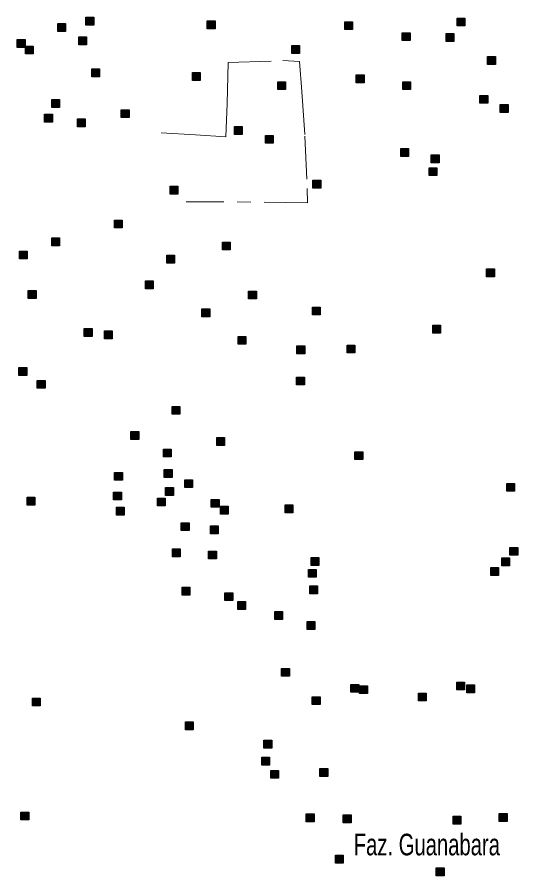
# Model space of a CAD drawing. Extents: x 445.6 to 500, y 8618.1 to 8673.4.
# Drawn here: x 461.6 to 465.3, y 8644.29 to 8650.65 of the extents above; entities that cross this region are included whole.
import ezdxf

# ---------------------------------------------------------------- set-up
doc = ezdxf.new("R2010")
doc.units = 0
doc.header["$LTSCALE"] = 0.064
doc.linetypes.add('DOT_DASHED', pattern=[7.7, 5, -1.2, 0.3, -1.2])
doc.layers.add('2', color=7, linetype='Continuous', lineweight=25)
doc.layers.add('22', color=7, linetype='DOT_DASHED', lineweight=13)
doc.layers.add('61', color=7, linetype='Continuous')

msp = doc.modelspace()

# ---------------------------------------------------------------- hatches: boundary and pattern name
at = {"layer": '2'}
for points in [[(462.1077, 8650.6478), (462.1657, 8650.6478), (462.1657, 8650.5898), (462.1077, 8650.5898)], [(464.8549, 8650.6411), (464.9129, 8650.6411), (464.9129, 8650.5831), (464.8549, 8650.5831)], [(461.9001, 8650.6003), (461.9581, 8650.6003), (461.9581, 8650.5423), (461.9001, 8650.5423)], [(463.0062, 8650.6207), (463.0642, 8650.6207), (463.0642, 8650.5627), (463.0062, 8650.5627)], [(464.0239, 8650.614), (464.0819, 8650.614), (464.0819, 8650.556), (464.0239, 8650.556)], [(462.0554, 8650.502), (462.1134, 8650.502), (462.1134, 8650.444), (462.0554, 8650.444)], [(464.4496, 8650.5327), (464.5076, 8650.5327), (464.5076, 8650.4747), (464.4496, 8650.4747)], [(464.7738, 8650.5259), (464.8318, 8650.5259), (464.8318, 8650.4679), (464.7738, 8650.4679)], [(461.5994, 8650.4817), (461.6574, 8650.4817), (461.6574, 8650.4237), (461.5994, 8650.4237)], [(463.6311, 8650.4377), (463.6891, 8650.4377), (463.6891, 8650.3797), (463.6311, 8650.3797)], [(461.6602, 8650.4343), (461.7182, 8650.4343), (461.7182, 8650.3763), (461.6602, 8650.3763)], [(465.0812, 8650.3565), (465.1392, 8650.3565), (465.1392, 8650.2985), (465.0812, 8650.2985)], [(462.1516, 8650.2649), (462.2096, 8650.2649), (462.2096, 8650.2069), (462.1516, 8650.2069)], [(462.897, 8650.2375), (462.955, 8650.2375), (462.955, 8650.1795), (462.897, 8650.1795)], [(464.1087, 8650.2205), (464.1667, 8650.2205), (464.1667, 8650.1625), (464.1087, 8650.1625)], [(463.5286, 8650.1697), (463.5866, 8650.1697), (463.5866, 8650.1117), (463.5286, 8650.1117)], [(464.4533, 8650.1697), (464.5113, 8650.1697), (464.5113, 8650.1117), (464.4533, 8650.1117)], [(465.0238, 8650.0685), (465.0818, 8650.0685), (465.0818, 8650.0105), (465.0238, 8650.0105)], [(461.8557, 8650.0378), (461.9137, 8650.0378), (461.9137, 8649.9798), (461.8557, 8649.9798)], [(465.1746, 8650.0007), (465.2326, 8650.0007), (465.2326, 8649.9427), (465.1746, 8649.9427)], [(461.8017, 8649.9294), (461.8597, 8649.9294), (461.8597, 8649.8714), (461.8017, 8649.8714)], [(462.3691, 8649.9633), (462.4271, 8649.9633), (462.4271, 8649.9053), (462.3691, 8649.9053)], [(462.0449, 8649.8955), (462.1029, 8649.8955), (462.1029, 8649.8375), (462.0449, 8649.8375)], [(463.2069, 8649.8377), (463.2649, 8649.8377), (463.2649, 8649.7797), (463.2069, 8649.7797)], [(463.4365, 8649.7733), (463.4945, 8649.7733), (463.4945, 8649.7153), (463.4365, 8649.7153)], [(464.4383, 8649.6754), (464.4963, 8649.6754), (464.4963, 8649.6174), (464.4383, 8649.6174)], [(464.6646, 8649.628), (464.7226, 8649.628), (464.7226, 8649.57), (464.6646, 8649.57)], [(464.6477, 8649.5331), (464.7057, 8649.5331), (464.7057, 8649.4751), (464.6477, 8649.4751)], [(463.7878, 8649.4413), (463.8458, 8649.4413), (463.8458, 8649.3833), (463.7878, 8649.3833)], [(462.7306, 8649.3973), (462.7886, 8649.3973), (462.7886, 8649.3393), (462.7306, 8649.3393)], [(462.3194, 8649.1466), (462.3774, 8649.1466), (462.3774, 8649.0886), (462.3194, 8649.0886)], [(461.8557, 8649.0146), (461.9137, 8649.0146), (461.9137, 8648.9566), (461.8557, 8648.9566)], [(463.119, 8648.9839), (463.177, 8648.9839), (463.177, 8648.9259), (463.119, 8648.9259)], [(461.6159, 8648.9164), (461.6739, 8648.9164), (461.6739, 8648.8584), (461.6159, 8648.8584)], [(462.7069, 8648.8857), (462.7649, 8648.8857), (462.7649, 8648.8277), (462.7069, 8648.8277)], [(465.0733, 8648.7844), (465.1313, 8648.7844), (465.1313, 8648.7264), (465.0733, 8648.7264)], [(462.5491, 8648.696), (462.6071, 8648.696), (462.6071, 8648.638), (462.5491, 8648.638)], [(461.681, 8648.6245), (461.739, 8648.6245), (461.739, 8648.5665), (461.681, 8648.5665)], [(463.3116, 8648.6214), (463.3696, 8648.6214), (463.3696, 8648.5634), (463.3116, 8648.5634)], [(462.967, 8648.4893), (463.025, 8648.4893), (463.025, 8648.4313), (462.967, 8648.4313)], [(463.7845, 8648.5028), (463.8425, 8648.5028), (463.8425, 8648.4448), (463.7845, 8648.4448)], [(462.0964, 8648.3436), (462.1544, 8648.3436), (462.1544, 8648.2856), (462.0964, 8648.2856)], [(464.6753, 8648.3681), (464.7333, 8648.3681), (464.7333, 8648.3101), (464.6753, 8648.3101)], [(462.2451, 8648.3267), (462.3031, 8648.3267), (462.3031, 8648.2687), (462.2451, 8648.2687)], [(463.2348, 8648.286), (463.2928, 8648.286), (463.2928, 8648.228), (463.2348, 8648.228)], [(463.6696, 8648.2148), (463.7276, 8648.2148), (463.7276, 8648.1568), (463.6696, 8648.1568)], [(464.0412, 8648.2216), (464.0992, 8648.2216), (464.0992, 8648.1636), (464.0412, 8648.1636)], [(461.6122, 8648.0553), (461.6702, 8648.0553), (461.6702, 8647.9973), (461.6122, 8647.9973)], [(461.7478, 8647.9598), (461.8058, 8647.9598), (461.8058, 8647.9018), (461.7478, 8647.9018)], [(463.6671, 8647.9843), (463.7251, 8647.9843), (463.7251, 8647.9263), (463.6671, 8647.9263)], [(462.7457, 8647.7673), (462.8037, 8647.7673), (462.8037, 8647.7093), (462.7457, 8647.7093)], [(462.4417, 8647.5809), (462.4997, 8647.5809), (462.4997, 8647.5229), (462.4417, 8647.5229)], [(463.0767, 8647.5369), (463.1347, 8647.5369), (463.1347, 8647.4789), (463.0767, 8647.4789)], [(462.6815, 8647.4522), (462.7395, 8647.4522), (462.7395, 8647.3942), (462.6815, 8647.3942)], [(464.0994, 8647.4321), (464.1574, 8647.4321), (464.1574, 8647.3741), (464.0994, 8647.3741)], [(462.3201, 8647.2794), (462.3781, 8647.2794), (462.3781, 8647.2214), (462.3201, 8647.2214)], [(462.6882, 8647.2997), (462.7462, 8647.2997), (462.7462, 8647.2417), (462.6882, 8647.2417)], [(462.8402, 8647.2252), (462.8982, 8647.2252), (462.8982, 8647.1672), (462.8402, 8647.1672)], [(465.2232, 8647.1983), (465.2812, 8647.1983), (465.2812, 8647.1403), (465.2232, 8647.1403)], [(462.3133, 8647.1337), (462.3713, 8647.1337), (462.3713, 8647.0757), (462.3133, 8647.0757)], [(462.6984, 8647.1676), (462.7564, 8647.1676), (462.7564, 8647.1096), (462.6984, 8647.1096)], [(461.6731, 8647.0955), (461.7311, 8647.0955), (461.7311, 8647.0375), (461.6731, 8647.0375)], [(462.6376, 8647.0897), (462.6956, 8647.0897), (462.6956, 8647.0317), (462.6376, 8647.0317)], [(463.0362, 8647.0795), (463.0942, 8647.0795), (463.0942, 8647.0215), (463.0362, 8647.0215)], [(462.3336, 8647.0219), (462.3916, 8647.0219), (462.3916, 8646.9639), (462.3336, 8646.9639)], [(463.1037, 8647.0287), (463.1617, 8647.0287), (463.1617, 8646.9707), (463.1037, 8646.9707)], [(463.5826, 8647.0391), (463.6406, 8647.0391), (463.6406, 8646.9811), (463.5826, 8646.9811)], [(462.8132, 8646.9067), (462.8712, 8646.9067), (462.8712, 8646.8487), (462.8132, 8646.8487)], [(463.0294, 8646.883), (463.0874, 8646.883), (463.0874, 8646.825), (463.0294, 8646.825)], [(462.749, 8646.7136), (462.807, 8646.7136), (462.807, 8646.6556), (462.749, 8646.6556)], [(463.0159, 8646.6967), (463.0739, 8646.6967), (463.0739, 8646.6387), (463.0159, 8646.6387)], [(465.2469, 8646.724), (465.3049, 8646.724), (465.3049, 8646.666), (465.2469, 8646.666)], [(463.7752, 8646.6495), (463.8332, 8646.6495), (463.8332, 8646.5915), (463.7752, 8646.5915)], [(465.1861, 8646.6461), (465.2441, 8646.6461), (465.2441, 8646.5881), (465.1861, 8646.5881)], [(463.7549, 8646.5614), (463.8129, 8646.5614), (463.8129, 8646.5034), (463.7549, 8646.5034)], [(465.105, 8646.5749), (465.163, 8646.5749), (465.163, 8646.5169), (465.105, 8646.5169)], [(463.765, 8646.4394), (463.823, 8646.4394), (463.823, 8646.3814), (463.765, 8646.3814)], [(462.82, 8646.429), (462.878, 8646.429), (462.878, 8646.371), (462.82, 8646.371)], [(463.1375, 8646.3883), (463.1955, 8646.3883), (463.1955, 8646.3303), (463.1375, 8646.3303)], [(463.2321, 8646.324), (463.2901, 8646.324), (463.2901, 8646.266), (463.2321, 8646.266)], [(463.5057, 8646.2494), (463.5637, 8646.2494), (463.5637, 8646.1914), (463.5057, 8646.1914)], [(463.7448, 8646.1751), (463.8028, 8646.1751), (463.8028, 8646.1171), (463.7448, 8646.1171)], [(463.5565, 8645.8292), (463.6145, 8645.8292), (463.6145, 8645.7712), (463.5565, 8645.7712)], [(464.07, 8645.7107), (464.128, 8645.7107), (464.128, 8645.6527), (464.07, 8645.6527)], [(464.1341, 8645.7005), (464.1921, 8645.7005), (464.1921, 8645.6425), (464.1341, 8645.6425)], [(464.853, 8645.7276), (464.911, 8645.7276), (464.911, 8645.6696), (464.853, 8645.6696)], [(464.9273, 8645.7073), (464.9853, 8645.7073), (464.9853, 8645.6493), (464.9273, 8645.6493)], [(461.7119, 8645.6088), (461.7699, 8645.6088), (461.7699, 8645.5508), (461.7119, 8645.5508)], [(463.7828, 8645.6192), (463.8408, 8645.6192), (463.8408, 8645.5612), (463.7828, 8645.5612)], [(464.5693, 8645.6463), (464.6273, 8645.6463), (464.6273, 8645.5883), (464.5693, 8645.5883)], [(462.8449, 8645.4328), (462.9029, 8645.4328), (462.9029, 8645.3748), (462.8449, 8645.3748)], [(463.4259, 8645.2973), (463.4839, 8645.2973), (463.4839, 8645.2393), (463.4259, 8645.2393)], [(463.409, 8645.1719), (463.467, 8645.1719), (463.467, 8645.1139), (463.409, 8645.1139)], [(463.4765, 8645.0737), (463.5345, 8645.0737), (463.5345, 8645.0157), (463.4765, 8645.0157)], [(463.8403, 8645.0873), (463.8983, 8645.0873), (463.8983, 8645.0293), (463.8403, 8645.0293)], [(461.6275, 8644.7652), (461.6855, 8644.7652), (461.6855, 8644.7072), (461.6275, 8644.7072)], [(463.7389, 8644.7518), (463.7969, 8644.7518), (463.7969, 8644.6938), (463.7389, 8644.6938)], [(464.0125, 8644.7451), (464.0705, 8644.7451), (464.0705, 8644.6871), (464.0125, 8644.6871)], [(464.826, 8644.7349), (464.884, 8644.7349), (464.884, 8644.6769), (464.826, 8644.6769)], [(465.1671, 8644.7552), (465.2251, 8644.7552), (465.2251, 8644.6972), (465.1671, 8644.6972)], [(463.9551, 8644.4469), (464.0131, 8644.4469), (464.0131, 8644.3889), (463.9551, 8644.3889)], [(464.701, 8644.3521), (464.759, 8644.3521), (464.759, 8644.2941), (464.701, 8644.2941)]]:
    msp.add_hatch(color=256, dxfattribs=at).paths.add_polyline_path(points)

# ---------------------------------------------------------------- linework, layer by layer
for points in [[(462.1077, 8650.6478), (462.1657, 8650.6478), (462.1657, 8650.5898), (462.1077, 8650.5898)], [(464.8549, 8650.6411), (464.9129, 8650.6411), (464.9129, 8650.5831), (464.8549, 8650.5831)], [(461.9001, 8650.6003), (461.9581, 8650.6003), (461.9581, 8650.5423), (461.9001, 8650.5423)], [(463.0062, 8650.6207), (463.0642, 8650.6207), (463.0642, 8650.5627), (463.0062, 8650.5627)], [(464.0239, 8650.614), (464.0819, 8650.614), (464.0819, 8650.556), (464.0239, 8650.556)], [(462.0554, 8650.502), (462.1134, 8650.502), (462.1134, 8650.444), (462.0554, 8650.444)], [(464.4496, 8650.5327), (464.5076, 8650.5327), (464.5076, 8650.4747), (464.4496, 8650.4747)], [(464.7738, 8650.5259), (464.8318, 8650.5259), (464.8318, 8650.4679), (464.7738, 8650.4679)], [(461.5994, 8650.4817), (461.6574, 8650.4817), (461.6574, 8650.4237), (461.5994, 8650.4237)], [(463.6311, 8650.4377), (463.6891, 8650.4377), (463.6891, 8650.3797), (463.6311, 8650.3797)], [(461.6602, 8650.4343), (461.7182, 8650.4343), (461.7182, 8650.3763), (461.6602, 8650.3763)], [(465.0812, 8650.3565), (465.1392, 8650.3565), (465.1392, 8650.2985), (465.0812, 8650.2985)], [(462.1516, 8650.2649), (462.2096, 8650.2649), (462.2096, 8650.2069), (462.1516, 8650.2069)], [(462.897, 8650.2375), (462.955, 8650.2375), (462.955, 8650.1795), (462.897, 8650.1795)], [(464.1087, 8650.2205), (464.1667, 8650.2205), (464.1667, 8650.1625), (464.1087, 8650.1625)], [(463.5286, 8650.1697), (463.5866, 8650.1697), (463.5866, 8650.1117), (463.5286, 8650.1117)], [(464.4533, 8650.1697), (464.5113, 8650.1697), (464.5113, 8650.1117), (464.4533, 8650.1117)], [(465.0238, 8650.0685), (465.0818, 8650.0685), (465.0818, 8650.0105), (465.0238, 8650.0105)], [(461.8557, 8650.0378), (461.9137, 8650.0378), (461.9137, 8649.9798), (461.8557, 8649.9798)], [(465.1746, 8650.0007), (465.2326, 8650.0007), (465.2326, 8649.9427), (465.1746, 8649.9427)], [(461.8017, 8649.9294), (461.8597, 8649.9294), (461.8597, 8649.8714), (461.8017, 8649.8714)], [(462.3691, 8649.9633), (462.4271, 8649.9633), (462.4271, 8649.9053), (462.3691, 8649.9053)], [(462.0449, 8649.8955), (462.1029, 8649.8955), (462.1029, 8649.8375), (462.0449, 8649.8375)], [(463.2069, 8649.8377), (463.2649, 8649.8377), (463.2649, 8649.7797), (463.2069, 8649.7797)], [(463.4365, 8649.7733), (463.4945, 8649.7733), (463.4945, 8649.7153), (463.4365, 8649.7153)], [(464.4383, 8649.6754), (464.4963, 8649.6754), (464.4963, 8649.6174), (464.4383, 8649.6174)], [(464.6646, 8649.628), (464.7226, 8649.628), (464.7226, 8649.57), (464.6646, 8649.57)], [(464.6477, 8649.5331), (464.7057, 8649.5331), (464.7057, 8649.4751), (464.6477, 8649.4751)], [(463.7878, 8649.4413), (463.8458, 8649.4413), (463.8458, 8649.3833), (463.7878, 8649.3833)], [(462.7306, 8649.3973), (462.7886, 8649.3973), (462.7886, 8649.3393), (462.7306, 8649.3393)], [(462.3194, 8649.1466), (462.3774, 8649.1466), (462.3774, 8649.0886), (462.3194, 8649.0886)], [(461.8557, 8649.0146), (461.9137, 8649.0146), (461.9137, 8648.9566), (461.8557, 8648.9566)], [(463.119, 8648.9839), (463.177, 8648.9839), (463.177, 8648.9259), (463.119, 8648.9259)], [(461.6159, 8648.9164), (461.6739, 8648.9164), (461.6739, 8648.8584), (461.6159, 8648.8584)], [(462.7069, 8648.8857), (462.7649, 8648.8857), (462.7649, 8648.8277), (462.7069, 8648.8277)], [(465.0733, 8648.7844), (465.1313, 8648.7844), (465.1313, 8648.7264), (465.0733, 8648.7264)], [(462.5491, 8648.696), (462.6071, 8648.696), (462.6071, 8648.638), (462.5491, 8648.638)], [(461.681, 8648.6245), (461.739, 8648.6245), (461.739, 8648.5665), (461.681, 8648.5665)], [(463.3116, 8648.6214), (463.3696, 8648.6214), (463.3696, 8648.5634), (463.3116, 8648.5634)], [(462.967, 8648.4893), (463.025, 8648.4893), (463.025, 8648.4313), (462.967, 8648.4313)], [(463.7845, 8648.5028), (463.8425, 8648.5028), (463.8425, 8648.4448), (463.7845, 8648.4448)], [(462.0964, 8648.3436), (462.1544, 8648.3436), (462.1544, 8648.2856), (462.0964, 8648.2856)], [(464.6753, 8648.3681), (464.7333, 8648.3681), (464.7333, 8648.3101), (464.6753, 8648.3101)], [(462.2451, 8648.3267), (462.3031, 8648.3267), (462.3031, 8648.2687), (462.2451, 8648.2687)], [(463.2348, 8648.286), (463.2928, 8648.286), (463.2928, 8648.228), (463.2348, 8648.228)], [(463.6696, 8648.2148), (463.7276, 8648.2148), (463.7276, 8648.1568), (463.6696, 8648.1568)], [(464.0412, 8648.2216), (464.0992, 8648.2216), (464.0992, 8648.1636), (464.0412, 8648.1636)], [(461.6122, 8648.0553), (461.6702, 8648.0553), (461.6702, 8647.9973), (461.6122, 8647.9973)], [(461.7478, 8647.9598), (461.8058, 8647.9598), (461.8058, 8647.9018), (461.7478, 8647.9018)], [(463.6671, 8647.9843), (463.7251, 8647.9843), (463.7251, 8647.9263), (463.6671, 8647.9263)], [(462.7457, 8647.7673), (462.8037, 8647.7673), (462.8037, 8647.7093), (462.7457, 8647.7093)], [(462.4417, 8647.5809), (462.4997, 8647.5809), (462.4997, 8647.5229), (462.4417, 8647.5229)], [(463.0767, 8647.5369), (463.1347, 8647.5369), (463.1347, 8647.4789), (463.0767, 8647.4789)], [(462.6815, 8647.4522), (462.7395, 8647.4522), (462.7395, 8647.3942), (462.6815, 8647.3942)], [(464.0994, 8647.4321), (464.1574, 8647.4321), (464.1574, 8647.3741), (464.0994, 8647.3741)], [(462.3201, 8647.2794), (462.3781, 8647.2794), (462.3781, 8647.2214), (462.3201, 8647.2214)], [(462.6882, 8647.2997), (462.7462, 8647.2997), (462.7462, 8647.2417), (462.6882, 8647.2417)], [(462.8402, 8647.2252), (462.8982, 8647.2252), (462.8982, 8647.1672), (462.8402, 8647.1672)], [(465.2232, 8647.1983), (465.2812, 8647.1983), (465.2812, 8647.1403), (465.2232, 8647.1403)], [(462.3133, 8647.1337), (462.3713, 8647.1337), (462.3713, 8647.0757), (462.3133, 8647.0757)], [(462.6984, 8647.1676), (462.7564, 8647.1676), (462.7564, 8647.1096), (462.6984, 8647.1096)], [(461.6731, 8647.0955), (461.7311, 8647.0955), (461.7311, 8647.0375), (461.6731, 8647.0375)], [(462.6376, 8647.0897), (462.6956, 8647.0897), (462.6956, 8647.0317), (462.6376, 8647.0317)], [(463.0362, 8647.0795), (463.0942, 8647.0795), (463.0942, 8647.0215), (463.0362, 8647.0215)], [(462.3336, 8647.0219), (462.3916, 8647.0219), (462.3916, 8646.9639), (462.3336, 8646.9639)], [(463.1037, 8647.0287), (463.1617, 8647.0287), (463.1617, 8646.9707), (463.1037, 8646.9707)], [(463.5826, 8647.0391), (463.6406, 8647.0391), (463.6406, 8646.9811), (463.5826, 8646.9811)], [(462.8132, 8646.9067), (462.8712, 8646.9067), (462.8712, 8646.8487), (462.8132, 8646.8487)], [(463.0294, 8646.883), (463.0874, 8646.883), (463.0874, 8646.825), (463.0294, 8646.825)], [(462.749, 8646.7136), (462.807, 8646.7136), (462.807, 8646.6556), (462.749, 8646.6556)], [(463.0159, 8646.6967), (463.0739, 8646.6967), (463.0739, 8646.6387), (463.0159, 8646.6387)], [(465.2469, 8646.724), (465.3049, 8646.724), (465.3049, 8646.666), (465.2469, 8646.666)], [(463.7752, 8646.6495), (463.8332, 8646.6495), (463.8332, 8646.5915), (463.7752, 8646.5915)], [(465.1861, 8646.6461), (465.2441, 8646.6461), (465.2441, 8646.5881), (465.1861, 8646.5881)], [(463.7549, 8646.5614), (463.8129, 8646.5614), (463.8129, 8646.5034), (463.7549, 8646.5034)], [(465.105, 8646.5749), (465.163, 8646.5749), (465.163, 8646.5169), (465.105, 8646.5169)], [(463.765, 8646.4394), (463.823, 8646.4394), (463.823, 8646.3814), (463.765, 8646.3814)], [(462.82, 8646.429), (462.878, 8646.429), (462.878, 8646.371), (462.82, 8646.371)], [(463.1375, 8646.3883), (463.1955, 8646.3883), (463.1955, 8646.3303), (463.1375, 8646.3303)], [(463.2321, 8646.324), (463.2901, 8646.324), (463.2901, 8646.266), (463.2321, 8646.266)], [(463.5057, 8646.2494), (463.5637, 8646.2494), (463.5637, 8646.1914), (463.5057, 8646.1914)], [(463.7448, 8646.1751), (463.8028, 8646.1751), (463.8028, 8646.1171), (463.7448, 8646.1171)], [(463.5565, 8645.8292), (463.6145, 8645.8292), (463.6145, 8645.7712), (463.5565, 8645.7712)], [(464.07, 8645.7107), (464.128, 8645.7107), (464.128, 8645.6527), (464.07, 8645.6527)], [(464.1341, 8645.7005), (464.1921, 8645.7005), (464.1921, 8645.6425), (464.1341, 8645.6425)], [(464.853, 8645.7276), (464.911, 8645.7276), (464.911, 8645.6696), (464.853, 8645.6696)], [(464.9273, 8645.7073), (464.9853, 8645.7073), (464.9853, 8645.6493), (464.9273, 8645.6493)], [(461.7119, 8645.6088), (461.7699, 8645.6088), (461.7699, 8645.5508), (461.7119, 8645.5508)], [(463.7828, 8645.6192), (463.8408, 8645.6192), (463.8408, 8645.5612), (463.7828, 8645.5612)], [(464.5693, 8645.6463), (464.6273, 8645.6463), (464.6273, 8645.5883), (464.5693, 8645.5883)], [(462.8449, 8645.4328), (462.9029, 8645.4328), (462.9029, 8645.3748), (462.8449, 8645.3748)], [(463.4259, 8645.2973), (463.4839, 8645.2973), (463.4839, 8645.2393), (463.4259, 8645.2393)], [(463.409, 8645.1719), (463.467, 8645.1719), (463.467, 8645.1139), (463.409, 8645.1139)], [(463.4765, 8645.0737), (463.5345, 8645.0737), (463.5345, 8645.0157), (463.4765, 8645.0157)], [(463.8403, 8645.0873), (463.8983, 8645.0873), (463.8983, 8645.0293), (463.8403, 8645.0293)], [(461.6275, 8644.7652), (461.6855, 8644.7652), (461.6855, 8644.7072), (461.6275, 8644.7072)], [(463.7389, 8644.7518), (463.7969, 8644.7518), (463.7969, 8644.6938), (463.7389, 8644.6938)], [(464.0125, 8644.7451), (464.0705, 8644.7451), (464.0705, 8644.6871), (464.0125, 8644.6871)], [(464.826, 8644.7349), (464.884, 8644.7349), (464.884, 8644.6769), (464.826, 8644.6769)], [(465.1671, 8644.7552), (465.2251, 8644.7552), (465.2251, 8644.6972), (465.1671, 8644.6972)], [(463.9551, 8644.4469), (464.0131, 8644.4469), (464.0131, 8644.3889), (463.9551, 8644.3889)], [(464.701, 8644.3521), (464.759, 8644.3521), (464.759, 8644.2941), (464.701, 8644.2941)]]:
    msp.add_lwpolyline(points, close=True, dxfattribs=at)
at = {"layer": '22'}
msp.add_lwpolyline([(462.6648, 8649.7922), (462.9196, 8649.7773), (463.1447, 8649.7617), (463.154, 8650.0084), (463.1603, 8650.3112), (463.5666, 8650.3268), (463.6885, 8650.3205), (463.7073, 8650.0989), (463.7292, 8649.768), (463.7448, 8649.3809), (463.7481, 8649.2732), (463.1011, 8649.2826), (462.8917, 8649.2826), (462.8511, 8649.2802)], dxfattribs=at)

# ---------------------------------------------------------------- texts
at = {"layer": '61', "width": 0.7}
msp.add_text('Faz. Guanabara', height=0.16, dxfattribs=at).set_placement((464.0903, 8644.4456))

doc.saveas('drawing.dxf')
